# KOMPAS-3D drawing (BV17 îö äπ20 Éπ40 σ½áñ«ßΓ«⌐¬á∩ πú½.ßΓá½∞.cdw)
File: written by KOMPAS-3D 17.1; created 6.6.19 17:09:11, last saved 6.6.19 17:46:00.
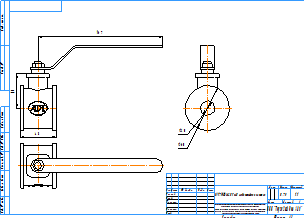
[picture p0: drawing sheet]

Sheet 1: A3, landscape

Title block, sheet 1: name: BV17 МФ Ду20 Ру40 хладостойкая угл.сталь; material: Сталь 20  ГОСТ 1050-2013; mass: 0,75; sheets: 1; sheet format: A3; stored path: C:\Users\kka\KOMPAS_Work\!Trash\BV17 МФ хладостойкая угл.сталь Ру40\KOMPAS 2D\BV17 МФ Ду20 Ру40 хладостойкая угл.сталь.cdw

Views: Вид 1, Проекционный вид 2, Проекционный вид 3
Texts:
  kka
  adl
  Рама для чертежей
  Лит-Масса-Масштаб
  Материал-Предприятие
  Масштаб
  Изм.
  Лист
  № докум.
  Подп.
  Дата
  Лит.
  Разраб.
  Пров.
  Т.контр.
  Листов
  Внимание! Данный продукт является объектом авторского права ООО «Торговый Дом АДЛ».
  Запрещается изменение, копирование, распространение
  (в том числе путем копирования на другие сайты и ресурсы в Интернете)
  или любое иное использование информации и объектов без предварительного
  согласия правообладателя (ООО «Торговый Дом АДЛ»).
  Н.контр.
  Утв.
  ООО "Торговый дом АДЛ"
  Изменение
  Номер документа
  Подпись
  Обозначение документа
  Наименование изделия
  Масса изделия по ГОСТ 2.109-73
  Порядковый номер листа
  Общее количество листов в документе
  Характер работы, выполненной лицом, подписавшим документ
  Наименование или индекс предприятия, выпускающего документ
  Инв. № подл.
  Подп. и дата
  Взам. инв. №
  Инв. № дубл.
  Инвентарный номер подлинника по ГОСТ 2.501-68
  Подпись принявшего подлинник в отдел технической документации
  Инвентарный номер подлинника, взамен которого выпущен данный подлинник
  Инвентарный номер дубликата по ГОСТ 2.502-68
  Подпись принявшего дубликат в отдел технической документации
  Справ. №
  Перв. примен.
  Обозначение документа, взамен или на основании которого выпущен данный документ
  Обозначение документа, в котором впервые записан данный документ
  Подпись лица, копировавшего чертеж
  Обозначение формата листа
  !Рама для чертежа
Dimensions and other numbers on the sheet: 48; 46; 167; 20; 60; 1:1; 1; 0,75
